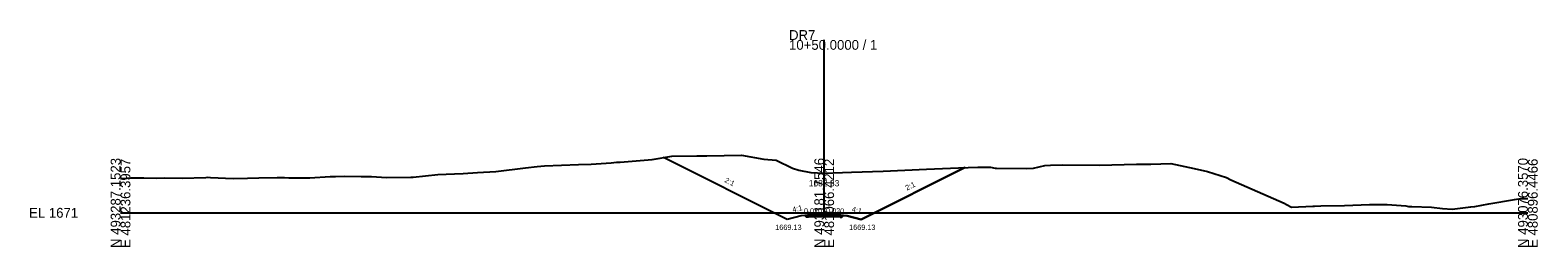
# Model space of a CAD drawing. Extents: x -26 to 403, y -10 to 4215.
# Drawn here: x -25.7 to 402.8, y 490.3 to 552 of the extents above; entities that cross this region are included whole.
import ezdxf

# ---------------------------------------------------------------- set-up
doc = ezdxf.new("R2010")
doc.units = 0
for name, color, linetype in [('Exist Cross Section Cell', 7, 'Continuous'), ('Exist XS Center Line Elevation Label', 7, 'Continuous'), ('Exist XS Ground Line', 7, 'Continuous'), ('Prop XS Ditch Slope Text', 7, 'Continuous'), ('Prop XS Ditch Standard Text', 7, 'Continuous'), ('Prop XS Dump Level', 7, 'Continuous'), ('Prop XS Earthwork Shape', 7, 'Continuous'), ('Prop XS EOT Tick Mark', 7, 'Continuous'), ('Prop XS Finish Grade', 7, 'Continuous'), ('Prop XS Finish Grade Earthwork', 7, 'Continuous'), ('Prop XS Finish Grade Pavement', 7, 'Continuous'), ('Prop XS Hydro Typical Ditch Data', 7, 'Continuous'), ('Prop XS Pvmt Edge Slope', 7, 'Continuous'), ('Prop XS SE Text', 7, 'Continuous'), ('Prop XS Shoulder Borrow Shape', 7, 'Continuous'), ('Prop XS Side Slope Text', 7, 'Continuous'), ('Prop XS Subgrade Earthwork', 7, 'Continuous')]:
    doc.layers.add(name, color=color, linetype=linetype)

msp = doc.modelspace()

# ---------------------------------------------------------------- linework, layer by layer
at = {"layer": 'Exist Cross Section Cell'}
for p, q in [((200, 500), (200, 549.19)), ((0, 500), (200, 500)), ((200, 500), (400, 500))]:
    msp.add_line(p, q, dxfattribs=at)
at = {"layer": 'Exist XS Ground Line'}
msp.add_lwpolyline([(0, 509.74), (0.75, 509.76), (2.99, 509.92), (6.6, 509.92), (10.25, 509.87), (12.52, 509.96), (17.52, 509.82), (24.28, 510.07), (24.78, 510.13), (25.58, 510.08), (32.05, 509.78), (36.05, 509.84), (39.31, 509.91), (44.56, 510.01), (46.57, 510.03), (47.82, 510), (53.84, 509.95), (59.59, 510.32), (61.1, 510.33), (63.54, 510.44), (68.37, 510.33), (71.36, 510.36), (75.63, 510.08), (82.52, 510.11), (83.13, 510.13), (90.16, 510.9), (94.9, 511.1), (97.42, 511.22), (101.5, 511.48), (106.67, 511.77), (115.1, 512.82), (118.43, 513.17), (120.48, 513.34), (130.2, 513.71), (133.75, 513.81), (139.46, 514.26), (141.01, 514.37), (141.97, 514.37), (151.11, 515.19), (156.71, 516.09), (163.77, 516.22), (166.63, 516.19), (176.5, 516.4), (182.8, 515.31), (186.39, 514.94), (190.96, 512.67), (192.82, 512.16), (196.23, 511.5), (200, 511.33), (207.77, 511.55), (216.74, 511.83), (229.07, 512.44), (238.18, 512.8), (243.64, 513.03), (247.22, 513), (248.6, 512.69), (248.95, 512.69), (257.39, 512.64), (259.45, 512.66), (262.73, 513.43), (264.35, 513.59), (267.87, 513.64), (278.25, 513.55), (288.75, 513.8), (292.88, 513.84), (298.53, 514.05), (305.12, 512.62), (308.93, 511.73), (314.32, 510.04), (315.62, 509.43), (330.71, 502.71), (331.42, 502.39), (332.82, 501.59), (338.89, 501.86), (339.37, 501.9), (341.13, 501.96), (347.93, 502.1), (354.99, 502.39), (355.96, 502.35), (356.47, 502.34), (360.04, 502.38), (365.3, 502), (366.04, 501.82), (366.98, 501.78), (372.6, 501.59), (375.77, 501.24), (378.53, 501), (383.82, 501.69), (384.96, 501.81), (388.87, 502.55), (396.24, 503.76), (397.96, 504.04), (399.21, 504.09), (400, 504.11)], dxfattribs=at)
at = {"layer": 'Prop XS Dump Level'}
for p, q in [((200, 499.38), (195.5, 499.29)), ((204.5, 499.29), (200, 499.38))]:
    msp.add_line(p, q, dxfattribs=at)
at = {"layer": 'Prop XS Earthwork Shape'}
msp.add_lwpolyline([(189.5, 498.13), (154.34, 515.71), (156.71, 516.09), (163.77, 516.22), (166.63, 516.19), (176.5, 516.4), (182.8, 515.31), (186.39, 514.94), (190.96, 512.67), (192.82, 512.16), (196.23, 511.5), (200, 511.33), (207.77, 511.55), (216.74, 511.83), (229.07, 512.44), (238.18, 512.8), (240, 512.88), (210.5, 498.13), (206.5, 499.13), (205.52, 499.21), (205.05, 498.74), (204.5, 498.75), (200, 498.84), (195.5, 498.75), (194.95, 498.74), (194.48, 499.21), (193.5, 499.13)], close=True, dxfattribs=at)
at = {"layer": 'Prop XS EOT Tick Mark'}
for p, q in [((195.5, 499.29), (195.5, 500.29)), ((204.5, 499.29), (204.5, 500.29))]:
    msp.add_line(p, q, dxfattribs=at)
at = {"layer": 'Prop XS Finish Grade'}
for p, q in [((195.5, 499.29), (194.48, 499.21)), ((204.5, 499.29), (205.52, 499.21))]:
    msp.add_line(p, q, dxfattribs=at)
at = {"layer": 'Prop XS Finish Grade Earthwork'}
for p, q in [((189.5, 498.13), (154.34, 515.71)), ((210.5, 498.13), (240, 512.88)), ((193.5, 499.13), (189.5, 498.13)), ((194.48, 499.21), (193.5, 499.13)), ((205.52, 499.21), (206.5, 499.13)), ((206.5, 499.13), (210.5, 498.13))]:
    msp.add_line(p, q, dxfattribs=at)
at = {"layer": 'Prop XS Finish Grade Pavement'}
for p, q in [((195.5, 499.29), (200, 499.38)), ((200, 499.38), (204.5, 499.29))]:
    msp.add_line(p, q, dxfattribs=at)
at = {"layer": 'Prop XS Hydro Typical Ditch Data'}
for p, q in [((189.5, 498.13), (154.34, 515.71)), ((210.5, 498.13), (240, 512.88)), ((193.5, 499.13), (189.5, 498.13)), ((206.5, 499.13), (210.5, 498.13))]:
    msp.add_line(p, q, dxfattribs=at)
at = {"layer": 'Prop XS Pvmt Edge Slope'}
for p, q in [((195.5, 499.29), (194.95, 498.74)), ((204.5, 499.29), (205.05, 498.74))]:
    msp.add_line(p, q, dxfattribs=at)
at = {"layer": 'Prop XS Shoulder Borrow Shape'}
for points in [[(195.5, 499.29), (194.95, 498.74), (194.48, 499.21)], [(195.5, 499.29), (194.95, 498.74), (194.48, 499.21)], [(205.05, 498.74), (205.52, 499.21), (204.5, 499.29)], [(205.05, 498.74), (205.52, 499.21), (204.5, 499.29)]]:
    msp.add_lwpolyline(points, close=True, dxfattribs=at)
at = {"layer": 'Prop XS Subgrade Earthwork'}
for p, q in [((194.95, 498.74), (194.48, 499.21)), ((195.5, 498.75), (194.95, 498.74)), ((200, 498.84), (195.5, 498.75)), ((204.5, 498.75), (200, 498.84)), ((204.5, 498.75), (205.05, 498.74)), ((205.05, 498.74), (205.52, 499.21))]:
    msp.add_line(p, q, dxfattribs=at)

# ---------------------------------------------------------------- texts
at = {"layer": 'Exist Cross Section Cell'}
for s, p in [('10+50.0000 / 1', (190, 546.39)), ('DR7', (190, 549.19)), ('EL 1671', (-26, 498.6))]:
    msp.add_text(s, height=2.8, dxfattribs=at).set_placement(p)
for s, p in [('N 493287.1523', (0, 490)), ('E 481236.3957', (2.8, 490)), ('N 493181.7546', (200, 490)), ('E 481066.4212', (202.8, 490)), ('N 493076.3570', (400, 490)), ('E 480896.4466', (402.8, 490))]:
    msp.add_text(s, height=2.8, rotation=90, dxfattribs=at).set_placement(p)
at = {"layer": 'Exist XS Center Line Elevation Label'}
msp.add_text('1682.33', height=1.8, dxfattribs=at).set_placement((195.6, 507.53))
at = {"layer": 'Prop XS Ditch Slope Text'}
for rotation, p in [(14.0362, (191.14, 500.09)), (345.9638, (207.71, 500.37))]:
    msp.add_text('4:1', height=1.5, rotation=rotation, dxfattribs=at).set_placement(p)
at = {"layer": 'Prop XS Ditch Standard Text'}
for p in [(186.08, 495.13), (207.08, 495.13)]:
    msp.add_text('1669.13', height=1.5, dxfattribs=at).set_placement(p)
at = {"layer": 'Prop XS Dump Level'}
for p in [(193.5, 499.09), (206.5, 499.09)]:
    msp.add_text('Case1', height=0.04, dxfattribs=at).set_placement(p)
at = {"layer": 'Prop XS SE Text'}
for rotation, p in [(1.1458, (194.26, 499.78)), (358.8542, (200.49, 499.89))]:
    msp.add_text('0.020', height=1.5, rotation=rotation, dxfattribs=at).set_placement(p)
at = {"layer": 'Prop XS Side Slope Text'}
for rotation, p in [(333.4349, (171.53, 508.79)), (26.5651, (223.51, 506.31))]:
    msp.add_text('2:1', height=1.5, rotation=rotation, dxfattribs=at).set_placement(p)

doc.saveas('drawing.dxf')
